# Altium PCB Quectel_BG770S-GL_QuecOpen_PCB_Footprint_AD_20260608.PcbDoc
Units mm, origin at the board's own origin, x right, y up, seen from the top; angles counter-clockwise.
Board outline 152.4 x 101.6 mm, 2 copper layers (Top Layer, Bottom Layer); 1 components, 0 nets, 94 pads, 0 vias.
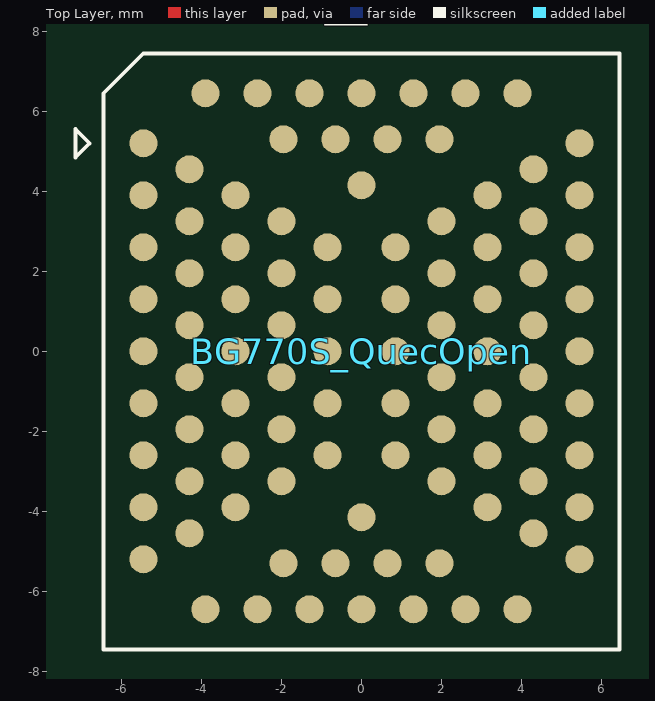
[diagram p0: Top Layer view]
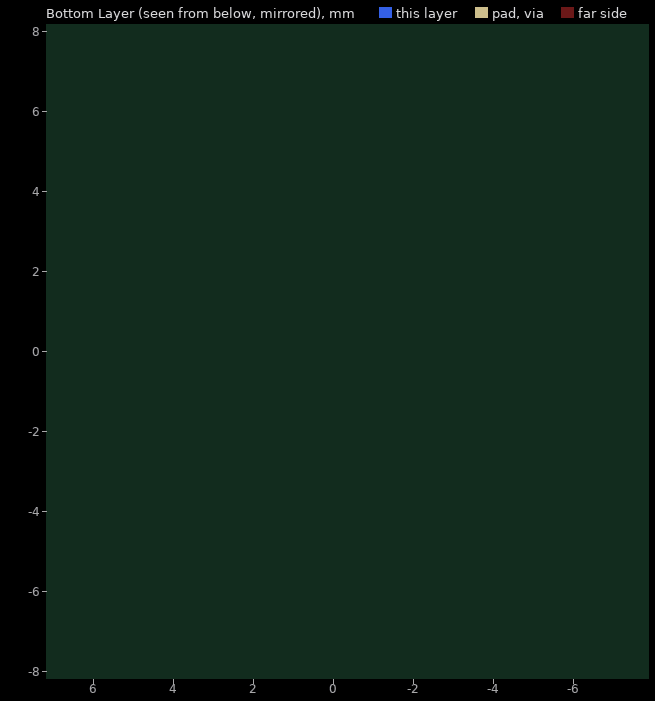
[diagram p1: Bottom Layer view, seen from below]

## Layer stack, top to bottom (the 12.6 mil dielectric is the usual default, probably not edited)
Top Solder: solder mask 0.0102, Solder Resist, Dk 3.5
Top Layer: signal copper 0.0356
Dielectric1: dielectric 0.32, FR-4, Dk 4.8
Bottom Layer: signal copper 0.0356
Bottom Solder: solder mask 0.0102, Solder Resist, Dk 3.5

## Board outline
-70.739,-53.721 81.661,-53.721 81.661,47.879 -70.739,47.879

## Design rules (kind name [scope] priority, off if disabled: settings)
Clearance [All] p1: gap=0.254 ignorepadtopadclearanceinfootprint=FALSE except(0: Arc-Hole Track-Hole SMDPad-Hole THPad-Hole Via-Hole Fill-Hole Poly-Hole Region-Hole Text-Hole)
PolygonConnect [All] p1: connectstyle=Relief reliefconductorwidth=0.254 reliefentries=4 polygonreliefangle="90 Angle" airgapwidth=0.254
RoutingVias [All] p1: holewidth=0.711 width=1.27 viastyle="Through Hole" minholewidth=0.711 minwidth=1.27 maxholewidth=0.711 maxwidth=1.27
SolderMaskExpansion [All] p1: expansion=0.102 istentingtop=FALSE
Width [All] p1: maxlimit=0.254 minlimit=0.254 preferedwidth=0.254
30 further rules are at their usual default settings.

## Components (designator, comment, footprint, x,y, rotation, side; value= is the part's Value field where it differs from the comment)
BG770S_QuecOpen "Comment" BG770S_QUECOPEN 0,0 r0 top

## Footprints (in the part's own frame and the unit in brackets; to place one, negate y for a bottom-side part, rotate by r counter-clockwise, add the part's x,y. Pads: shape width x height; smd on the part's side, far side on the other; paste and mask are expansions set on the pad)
BG770S_QUECOPEN [mm]
  round 0.7 smd mask+0.05: 1(-5.45,5.2) 2(-5.45,3.9) 3(-5.45,2.6) 4(-5.45,1.3) 5(-5.45,0) 6(-5.45,-1.3) 7(-5.45,-2.6) 8(-5.45,-3.9) 9(-5.45,-5.2) 10(-3.9,-6.45) 11(-2.6,-6.45) 12(-1.3,-6.45) 13(0,-6.45) 14(1.3,-6.45) 15(2.6,-6.45) 16(3.9,-6.45) 17(5.45,-5.2) 18(5.45,-3.9) 19(5.45,-2.6) 20(5.45,-1.3) 21(5.45,0) 22(5.45,1.3) 23(5.45,2.6) 24(5.45,3.9) 25(5.45,5.2) 26(3.9,6.45) 27(2.6,6.45) 28(1.3,6.45) 29(0,6.45) 30(-1.3,6.45) 31(-2.6,6.45) 32(-3.9,6.45) 33(-4.3,4.55) 34(-4.3,3.25) 35(-4.3,1.95) 36(-4.3,0.65) 37(-4.3,-0.65) 38(-4.3,-1.95) 39(-4.3,-3.25) 40(-4.3,-4.55) 41(-1.95,-5.3) 42(-0.65,-5.3) 43(0.65,-5.3) 44(1.95,-5.3) 45(4.3,-4.55) 46(4.3,-3.25) 47(4.3,-1.95) 48(4.3,-0.65) 49(4.3,0.65) 50(4.3,1.95) 51(4.3,3.25) 52(4.3,4.55) 53(1.95,5.3) 54(0.65,5.3) 55(-0.65,5.3) 56(-1.95,5.3) 57(-3.15,3.9) 58(-3.15,2.6) 59(-3.15,1.3) 60(-3.15,0) 61(-3.15,-1.3) 62(-3.15,-2.6) 63(-3.15,-3.9) 64(0,-4.15) 65(3.15,-3.9) 66(3.15,-2.6) 67(3.15,-1.3) 68(3.15,0) 69(3.15,1.3) 70(3.15,2.6) 71(3.15,3.9) 72(0,4.15) 73(-2,3.25) 74(-2,1.95) 75(-2,0.65) 76(-2,-0.65) 77(-2,-1.95) 78(-2,-3.25) 79(2,-3.25) 80(2,-1.95) 81(2,-0.65) 82(2,0.65) 83(2,1.95) 84(2,3.25) 85(-0.85,2.6) 86(-0.85,1.3) 87(-0.85,0) 88(-0.85,-1.3) 89(-0.85,-2.6) 90(0.85,-2.6) 91(0.85,-1.3) 92(0.85,0) 93(0.85,1.3) 94(0.85,2.6)
  silkscreen extent -7.15,-7.45 6.45,7.45

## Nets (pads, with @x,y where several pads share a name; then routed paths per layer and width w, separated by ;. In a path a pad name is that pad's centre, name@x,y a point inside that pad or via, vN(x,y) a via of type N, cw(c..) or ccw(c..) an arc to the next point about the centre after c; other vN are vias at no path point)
pads on no net: BG770S_QuecOpen.1 BG770S_QuecOpen.2 BG770S_QuecOpen.3 BG770S_QuecOpen.4 BG770S_QuecOpen.5 BG770S_QuecOpen.6 BG770S_QuecOpen.7 BG770S_QuecOpen.8 BG770S_QuecOpen.9 BG770S_QuecOpen.10 BG770S_QuecOpen.11 BG770S_QuecOpen.12 BG770S_QuecOpen.13 BG770S_QuecOpen.14 BG770S_QuecOpen.15 BG770S_QuecOpen.16 BG770S_QuecOpen.17 BG770S_QuecOpen.18 BG770S_QuecOpen.19 BG770S_QuecOpen.20 BG770S_QuecOpen.21 BG770S_QuecOpen.22 BG770S_QuecOpen.23 BG770S_QuecOpen.24 BG770S_QuecOpen.25 BG770S_QuecOpen.26 BG770S_QuecOpen.27 BG770S_QuecOpen.28 BG770S_QuecOpen.29 BG770S_QuecOpen.30 BG770S_QuecOpen.31 BG770S_QuecOpen.32 BG770S_QuecOpen.33 BG770S_QuecOpen.34 BG770S_QuecOpen.35 BG770S_QuecOpen.36 BG770S_QuecOpen.37 BG770S_QuecOpen.38 BG770S_QuecOpen.39 BG770S_QuecOpen.40 BG770S_QuecOpen.41 BG770S_QuecOpen.42 BG770S_QuecOpen.43 BG770S_QuecOpen.44 BG770S_QuecOpen.45 BG770S_QuecOpen.46 BG770S_QuecOpen.47 BG770S_QuecOpen.48 BG770S_QuecOpen.49 BG770S_QuecOpen.50 BG770S_QuecOpen.51 BG770S_QuecOpen.52 BG770S_QuecOpen.53 BG770S_QuecOpen.54 BG770S_QuecOpen.55 BG770S_QuecOpen.56 BG770S_QuecOpen.57 BG770S_QuecOpen.58 BG770S_QuecOpen.59 BG770S_QuecOpen.60 BG770S_QuecOpen.61 BG770S_QuecOpen.62 BG770S_QuecOpen.63 BG770S_QuecOpen.64 BG770S_QuecOpen.65 BG770S_QuecOpen.66 BG770S_QuecOpen.67 BG770S_QuecOpen.68 BG770S_QuecOpen.69 BG770S_QuecOpen.70 BG770S_QuecOpen.71 BG770S_QuecOpen.72 BG770S_QuecOpen.73 BG770S_QuecOpen.74 BG770S_QuecOpen.75 BG770S_QuecOpen.76 BG770S_QuecOpen.77 BG770S_QuecOpen.78 BG770S_QuecOpen.79 BG770S_QuecOpen.80 BG770S_QuecOpen.81 BG770S_QuecOpen.82 BG770S_QuecOpen.83 BG770S_QuecOpen.84 BG770S_QuecOpen.85 BG770S_QuecOpen.86 BG770S_QuecOpen.87 BG770S_QuecOpen.88 BG770S_QuecOpen.89 BG770S_QuecOpen.90 BG770S_QuecOpen.91 BG770S_QuecOpen.92 BG770S_QuecOpen.93 BG770S_QuecOpen.94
